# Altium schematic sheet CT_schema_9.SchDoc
size 281 x 153 mm
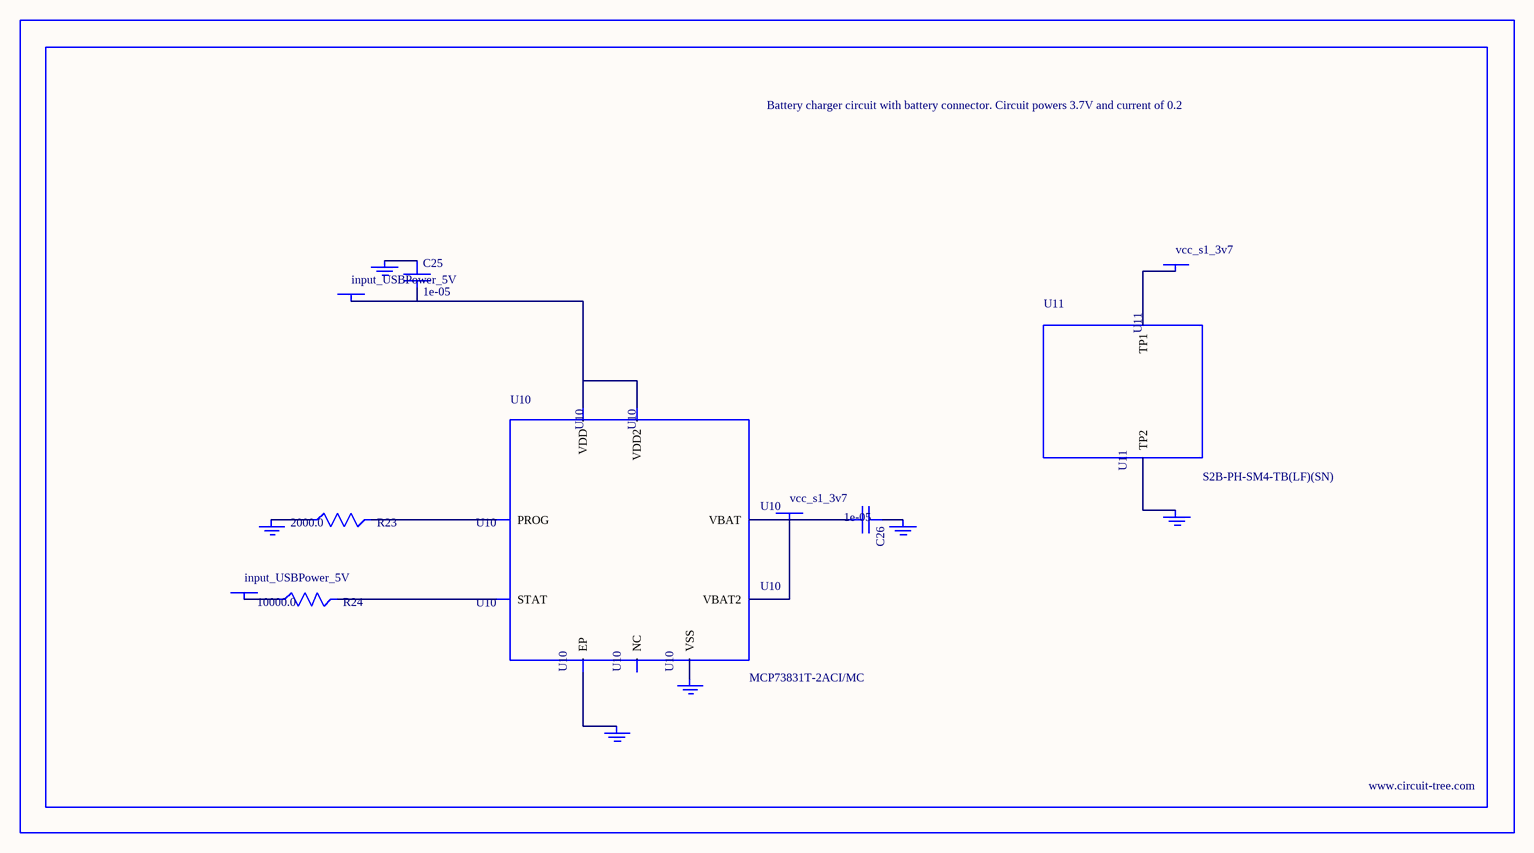
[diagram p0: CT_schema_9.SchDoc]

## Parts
BORDER8  (no value)
C25  1e-05  [C1206]
C26  1e-05  [C1206]
GND_INSTANCE_8_0  (no value)
GND_INSTANCE_8_1  (no value)
GND_INSTANCE_8_2  (no value)
GND_INSTANCE_8_3  (no value)
GND_INSTANCE_8_4  (no value)
GND_INSTANCE_8_5  (no value)
POWER_INSTANCE_8_0  input_USBPower_5V
POWER_INSTANCE_8_1  input_USBPower_5V
POWER_INSTANCE_8_2  vcc_s1_3v7
POWER_INSTANCE_8_3  vcc_s1_3v7
R23  2000.0  [R0603]
R24  10000.0  [R0603]
U10  MCP73831T-2ACI/MC  [DFN8_2X3MC]
U11  S2B-PH-SM4-TB(LF)(SN)  [JST-2-SMD]

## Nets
NetC25_1: C25.1 GND_INSTANCE_8_0.0(GND)
NetC25_2: C25.2 POWER_INSTANCE_8_0.0(PWR) U10.1(VDD) U10.2(VDD2)
NetC26_1: C26.1 GND_INSTANCE_8_1.0(GND)
NetC26_2: C26.2 POWER_INSTANCE_8_2.0(PWR) U10.3(VBAT) U10.4(VBAT2)
NetGND_INSTANCE_8_2_0: GND_INSTANCE_8_2.0(GND) R23.1
NetGND_INSTANCE_8_3_0: GND_INSTANCE_8_3.0(GND) U10.9(EP)
NetGND_INSTANCE_8_4_0: GND_INSTANCE_8_4.0(GND) U10.6(VSS)
NetGND_INSTANCE_8_5_0: GND_INSTANCE_8_5.0(GND) U11.2(TP2)
NetPOWER_INSTANCE_8_1_0: POWER_INSTANCE_8_1.0(PWR) R24.1
NetPOWER_INSTANCE_8_3_0: POWER_INSTANCE_8_3.0(PWR) U11.1(TP1)
NetR23_2: R23.2 U10.8(PROG)
NetR24_2: R24.2 U10.5(STAT)

Not connected (* = marked no-connect by the designer): U10 7(NC)

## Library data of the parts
BORDER8 = BORDER_PAGE8
C25 C26 = C1206C106K3RACTU
GND_INSTANCE_8_0-GND_INSTANCE_8_5 = GND
POWER_INSTANCE_8_0-POWER_INSTANCE_8_3 = PWR
R23 = RC0603JR-072KL
R24 = RC0603JR-0710KL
